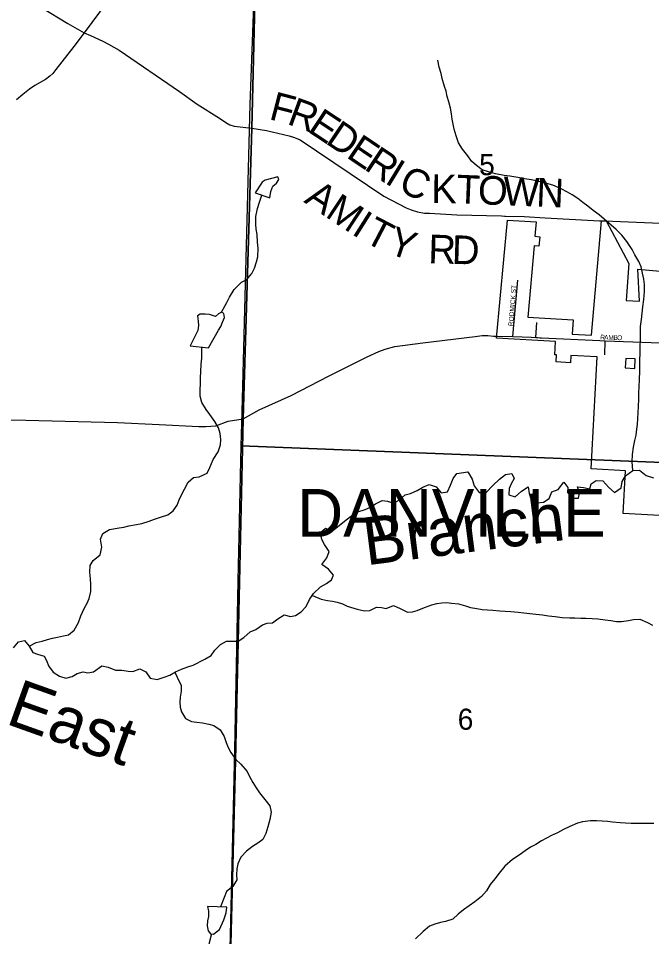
# Model space of a CAD drawing. Extents: x 1759416 to 2214760, y 252598 to 1116833.
# Drawn here: x 2027466 to 2034103, y 885483 to 895108 of the extents above; entities that cross this region are included whole.
import ezdxf

# ---------------------------------------------------------------- set-up
doc = ezdxf.new("R2010")
doc.units = 0
for name, color, linetype in [('GM_X_City_Street', 7, 'Continuous'), ('GM_X_City_Street_Text', 7, 'Continuous'), ('GM_X_Corporation', 7, 'Continuous'), ('GM_X_Corporation_Text', 7, 'Continuous'), ('GM_X_County_Road', 7, 'Continuous'), ('GM_X_County_Road_Text', 7, 'Continuous'), ('GM_X_Minor_Lake', 7, 'Continuous'), ('GM_X_Minor_River', 7, 'Continuous'), ('GM_X_Minor_River_Text', 7, 'Continuous'), ('GM_X_Section', 7, 'Continuous'), ('GM_X_Section_Text', 7, 'Continuous'), ('GM_X_Township', 7, 'Continuous'), ('GM_X_Township_Road', 7, 'Continuous'), ('GM_X_Township_ROW', 7, 'Continuous')]:
    doc.layers.add(name, color=color, linetype=linetype)

msp = doc.modelspace()

# ---------------------------------------------------------------- linework, layer by layer
at = {"layer": 'GM_X_City_Street'}
for points in [[(2032647.8, 891772.5), (2032699.7, 892363.5)], [(2032888.5, 891763.3), (2032898.6, 891921)], [(2032446.7, 891778.4), (2032478, 891776.3), (2032647.8, 891772.5), (2032746, 891770.2), (2032839.5, 891765.7), (2032888.5, 891763.3), (2032908.1, 891762.3), (2032932.8, 891760.9), (2032948.6, 891759.8), (2033559, 891730.3), (2033617.6, 891728.1), (2034387.6, 891699), (2034404.7, 891698.4)], [(2033612.6, 891579.4), (2033617.6, 891728.1)]]:
    msp.add_lwpolyline(points, dxfattribs=at)
at = {"layer": 'GM_X_Corporation'}
msp.add_lwpolyline([(2034633.1, 889872.7), (2033805.7, 889916.9), (2033829.4, 890366.4), (2033469.8, 890385.2), (2033531.4, 891558.8), (2033256.8, 891573.2), (2033252.9, 891498.3), (2033103, 891506.2), (2033107, 891581.1), (2033087, 891582.1), (2033094.4, 891721.9), (2032476, 891754.4), (2032591.4, 892992.4), (2032892.1, 892975.8), (2032880, 892823.7), (2032929.8, 892819.3), (2032921.1, 892719.7), (2032871.3, 892724.1), (2032805.8, 891976.8), (2033280, 891947.8), (2033270.8, 891798), (2033471, 891785.7), (2033578.2, 892985.8), (2033627.2, 892983.9), (2033864.7, 892537), (2033837.7, 892150.9), (2033976.7, 892143.1), (2033959.1, 892479.6), (2034233.1, 892455.7)], dxfattribs=at)
msp.add_lwpolyline([(2033926.2, 891437.8), (2033931.4, 891537.7), (2033831.5, 891542.9), (2033826.3, 891443.1)], close=True, dxfattribs=at)
at = {"layer": 'GM_X_County_Road'}
for points in [[(2028907.5, 896004.4), (2028898.5, 895993.8), (2028819.8, 895886.9), (2028546.2, 895485.6), (2028157, 894956.9), (2028046.7, 894812.8), (2027860.4, 894570.6), (2027826.3, 894528.5), (2027796.3, 894500.5), (2027752.2, 894468.5), (2027640.1, 894404.5), (2027582, 894366.6), (2027511.9, 894308.5), (2027445.8, 894252.5)], [(2027445, 895368.5), (2027583, 895294.1), (2027707, 895221.9), (2027983, 895053.3), (2028157, 894956.9), (2028222.9, 894926.8), (2028351, 894868.5), (2028411, 894836.4), (2028523, 894774.2), (2029154.9, 894342.7), (2029338.8, 894208.2), (2029574.8, 894061.7), (2029640.8, 894015.5), (2029682.8, 893993.4), (2029728.8, 893977.3), (2029912.9, 893957.5)], [(2029912.9, 893957.5), (2030067.9, 893933.9), (2030303, 893876.5), (2030361, 893860.4), (2030421, 893834.3), (2031296.9, 893244.2), (2031530.4, 893123.6), (2031582.2, 893102.2), (2031649.8, 893081.5), (2031724.2, 893067.6), (2031760, 893065.7), (2031776.2, 893064.8)], [(2031776.2, 893064.8), (2032061.1, 893050.2), (2032529.3, 893036.4), (2032562.3, 893035.4)], [(2032562.3, 893035.4), (2032570.8, 893035.1), (2032765.8, 893029.4), (2032985.4, 893018.7), (2033557.6, 892987.3)], [(2033557.6, 892987.3), (2033597.9, 892985.1), (2033610, 892984.6)], [(2033610, 892984.6), (2034448.4, 892950.1)], [(2029821.1, 890910.4), (2029990.8, 891005.5), (2030324.1, 891153.7), (2030722.6, 891359.6), (2031123, 891561.5), (2031245.2, 891615.4), (2031309.2, 891639.4), (2031413.3, 891669.4), (2031705.5, 891705.1), (2032253.9, 891772.6), (2032325.9, 891782.5), (2032386, 891782.4), (2032446.7, 891778.4)], [(2026673.8, 890913.6), (2027544.3, 890894.5), (2028504.8, 890873.3), (2028941, 890850.8), (2029359.2, 890830.3), (2029431.3, 890830.2), (2029537.3, 890836.1), (2029664.2, 890884.7), (2029821.1, 890910.4)]]:
    msp.add_lwpolyline(points, dxfattribs=at)
at = {"layer": 'GM_X_Minor_Lake'}
for points in [[(2030100.4, 893228.1), (2030112.1, 893294.3), (2030134, 893350.5), (2030169.9, 893380.7), (2030195.8, 893418.9), (2030183.7, 893446.9), (2030053.6, 893412.4), (2030021.6, 893390.2), (2029948, 893277.7)], [(2029948, 893277.7), (2030100.4, 893228.1)], [(2029457.4, 891652.7), (2029562.9, 891839.4), (2029586.7, 891879.6), (2029606.6, 891923.7), (2029626.4, 891973.9), (2029620.3, 892016), (2029594.2, 892029.9), (2029564.2, 892011.8), (2029532.3, 891983.6), (2029468.1, 892003.4), (2029424, 892007.3), (2029372, 892007.1), (2029344, 891989), (2029352.2, 891934.9), (2029354.4, 891886.8), (2029348.6, 891836.7), (2029265.1, 891674)], [(2029265.1, 891674), (2029457.4, 891652.7)], [(2029447.4, 885798.3), (2029459.6, 885750.2), (2029459.8, 885694.1), (2029450, 885648), (2029446.2, 885595.9), (2029454.4, 885541.8), (2029480.5, 885511.8), (2029510.6, 885507.9), (2029572.5, 885558.2), (2029620.2, 885658.6), (2029643.9, 885732.8), (2029649.7, 885793)], [(2029649.7, 885793), (2029447.4, 885798.3)]]:
    msp.add_lwpolyline(points, dxfattribs=at)
at = {"layer": 'GM_X_Minor_River'}
for points in [[(2033906.5, 890367.1), (2033900.2, 890459.3), (2033903.9, 890537.4), (2033913.6, 890611.6), (2033927.4, 890681.8), (2033939.2, 890740), (2033946.9, 890802.2), (2033954.8, 890852.3), (2033958.5, 890912.4), (2033962.3, 890976.6), (2033964.1, 891040.7), (2033967.8, 891114.9), (2033969.6, 891181), (2033973.3, 891245.2), (2033975, 891323.3), (2033978.7, 891411.5), (2033980.3, 891523.8), (2033982, 891599.9), (2033983.7, 891672.1), (2033985.5, 891736.2), (2033985.2, 891820.4), (2033986.9, 891878.5), (2033996.7, 891952.7), (2034004.4, 892016.9), (2034012.2, 892085.1), (2034021.9, 892159.3), (2034027.6, 892245.5), (2034029.3, 892319.6), (2034021.1, 892375.7), (2034008.9, 892437.8), (2033992.6, 892501.9), (2033968.3, 892559.9), (2033926, 892627.9), (2033897.8, 892683.9), (2033841.4, 892767.9), (2033789.1, 892833.9), (2033732.8, 892893.8), (2033678.5, 892939.7), (2033604.2, 893001.6), (2033551.9, 893047.5), (2033489.6, 893095.4), (2033433.4, 893139.3), (2033381.2, 893179.2), (2033331, 893219.1), (2033270.7, 893257), (2033220.6, 893286.9), (2033156.3, 893322.7), (2033068.1, 893358.5), (2033005.9, 893378.3), (2032921.7, 893398.1), (2032845.5, 893413.9), (2032771.4, 893425.7), (2032699.2, 893439.4), (2032617.1, 893455.2), (2032559, 893461), (2032466.8, 893478.7), (2032392.6, 893498.5), (2032326.4, 893520.3), (2032266.2, 893564.2), (2032215.9, 893612.1), (2032175.6, 893666.1), (2032119.3, 893738.1), (2032079, 893804.1), (2032052.7, 893876.1), (2032034.4, 893946.2), (2032024.2, 893998.3), (2032013.9, 894052.4), (2032005.7, 894106.4), (2031995.5, 894166.5), (2031979.2, 894234.6), (2031961, 894288.7), (2031948.7, 894344.8), (2031932.5, 894394.8), (2031908.2, 894478.9), (2031898, 894529), (2031877.7, 894597), (2031861.4, 894669.1)], [(2029596.7, 892028.6), (2029651.9, 892130.3), (2029679.7, 892184.5), (2029729.5, 892264.9), (2029805.3, 892343.3), (2029861.3, 892369.5), (2029913.1, 892433.8), (2029940.9, 892488), (2029962.7, 892554.2), (2029974.5, 892608.4), (2029978.2, 892698.6), (2029973.9, 892762.7), (2029967.6, 892842.9), (2029959.4, 892897), (2029955.2, 892949.1), (2029954.9, 893031.2), (2029972.6, 893113.5), (2029994.4, 893181.7), (2030017.9, 893255)], [(2027578.6, 888525.7), (2027652.5, 888566), (2027716.5, 888580.3), (2027772.6, 888596.5), (2027822.6, 888610.7), (2027874.6, 888620.9), (2027940.6, 888635.2), (2027990.7, 888647.4), (2028052.6, 888693.7), (2028096.3, 888774), (2028120.1, 888846.2), (2028155.9, 888922.5), (2028185.7, 888976.7), (2028209.6, 889026.9), (2028225.3, 889099.1), (2028225, 889175.3), (2028220.8, 889233.4), (2028216.5, 889303.5), (2028218.3, 889371.7), (2028250.1, 889423.9), (2028324, 889486.3), (2028341.7, 889566.5), (2028327.4, 889648.6), (2028351.2, 889706.8), (2028421.1, 889751.1), (2028521.2, 889767.5), (2028571.2, 889773.7), (2028625.3, 889787.9), (2028703.3, 889804.2), (2028761.4, 889814.4), (2028835.4, 889836.7), (2028893.4, 889859), (2028955.4, 889879.2), (2029031.4, 889905.5), (2029087.3, 889945.8), (2029131.2, 890004.1), (2029153, 890060.3), (2029176.8, 890114.5), (2029206.6, 890172.7), (2029244.4, 890247), (2029300.3, 890295.3), (2029362.4, 890301.5), (2029444.3, 890341.9), (2029472.2, 890400.1), (2029507.9, 890482.4), (2029561.7, 890564.7), (2029585.4, 890639), (2029587.2, 890695.1), (2029581, 890755.2), (2029562.7, 890817.3), (2029526.4, 890883.3), (2029472.1, 890957.2), (2029435.8, 891009.2), (2029389.5, 891081.2), (2029371.2, 891147.3), (2029372.9, 891213.4), (2029376.7, 891279.6), (2029376.5, 891341.7), (2029378.2, 891401.8), (2029381.9, 891484), (2029387.7, 891546.2), (2029389.3, 891660.2)], [(2027735.2, 888424), (2027763.4, 888370), (2027783.6, 888320), (2027831.9, 888254), (2027896.2, 888214.1), (2027964.4, 888192.3), (2028028.4, 888210.6), (2028082.3, 888240.8), (2028144.4, 888257.1), (2028194.5, 888249.2), (2028254.5, 888259.4), (2028342.4, 888321.9), (2028408.5, 888308.1), (2028484.8, 888276.2), (2028548.8, 888276.5), (2028617, 888266.7), (2028667.1, 888260.8), (2028739.1, 888291.1), (2028801.3, 888257.3), (2028847.6, 888193.3), (2028919.7, 888177.5), (2028995.7, 888203.8), (2029053.8, 888224.1), (2029113.7, 888258.3), (2029175.7, 888286.6), (2029243.7, 888310.9), (2029297.7, 888329.1), (2029421.6, 888391.7), (2029487.6, 888428), (2029525.4, 888484.2), (2029585.3, 888544.5), (2029647.2, 888580.8), (2029697.3, 888581), (2029771.4, 888579.2), (2029827.4, 888619.5), (2029897.2, 888677.9), (2029953.2, 888702.1), (2030025.1, 888750.5), (2030075.1, 888766.7), (2030129.2, 888770.9), (2030187.1, 888815.2), (2030251.1, 888855.5), (2030319.2, 888837.7), (2030369.3, 888847.9), (2030429.2, 888886.1), (2030481.1, 888942.4), (2030516.8, 889014.7), (2030560.7, 889079), (2030632.5, 889149.4), (2030696.4, 889183.7), (2030748.4, 889221.9), (2030770.2, 889272.1), (2030715.9, 889334.1), (2030647.6, 889381.9), (2030697.4, 889454.2), (2030723.2, 889520.5), (2030674.9, 889592.5), (2030646.6, 889644.5), (2030632.4, 889718.6), (2030684.3, 889764.9), (2030748.5, 889729), (2030810.4, 889777.3), (2030884.3, 889837.7), (2030948.2, 889888), (2031022.1, 889934.4), (2031100.1, 889960.7), (2031158.1, 889982.9), (2031210, 890019.2), (2031280, 890053.5), (2031334.1, 890045.7), (2031396.3, 890025.8), (2031460.2, 890060.1), (2031520.1, 890114.4), (2031574.1, 890128.7), (2031646.1, 890159), (2031706.1, 890195.2), (2031772.1, 890223.5), (2031844.3, 890197.7), (2031896.6, 890135.8), (2031962.6, 890144), (2031994.4, 890214.3), (2032024.2, 890284.5), (2032062, 890336.8), (2032178.1, 890355.2), (2032220.5, 890279.2), (2032242.8, 890207.1), (2032295.1, 890139.1), (2032367.2, 890137.4), (2032439, 890211.8), (2032508.9, 890276.1), (2032572.8, 890326.5), (2032638.8, 890336.7), (2032661.1, 890284.7), (2032629.2, 890230.5), (2032609.4, 890180.3), (2032607.6, 890112.1), (2032671.8, 890094.3), (2032739.7, 890152.7), (2032807.6, 890197), (2032817.9, 890126.9), (2032836.1, 890070.8)], [(2032836.1, 890070.8), (2032904.4, 890031), (2032970.4, 890037.2), (2033028.4, 890075.5), (2033056.2, 890145.7), (2033124.2, 890170), (2033184, 890246.4), (2033226.2, 890190.4), (2033222.4, 890136.3), (2033272.7, 890078.3), (2033336.8, 890078.5), (2033348.6, 890132.7), (2033326.3, 890198.8), (2033390.5, 890191), (2033456.6, 890177.2), (2033470.4, 890227.3), (2033522.4, 890263.6), (2033592.5, 890261.8), (2033654.8, 890189.9), (2033713.1, 890137.9), (2033785, 890188.3), (2033794.8, 890254.5), (2033828.6, 890312.7), (2033906.5, 890367.1), (2033974.6, 890371.3), (2034044.9, 890317.5), (2034121.1, 890291.7)], [(2030547.7, 889060), (2030641, 889021.1), (2030707.1, 889005.3), (2030757.2, 888997.5), (2030807.3, 888987.6), (2030861.5, 888971.8), (2030911.6, 888947.9), (2031015.9, 888916.2), (2031092.1, 888896.4), (2031150.1, 888902.6), (2031218.1, 888936.9), (2031270.2, 888933.1), (2031322.3, 888923.3), (2031398.3, 888953.6), (2031466.5, 888923.8), (2031544.8, 888883.9), (2031596.8, 888886.1), (2031646.8, 888900.3), (2031722.8, 888932.6), (2031798.8, 888960.9), (2031852.9, 888973.2), (2031904.9, 888981.3), (2031957, 888983.5), (2032007.1, 888979.7), (2032079.2, 888971.9), (2032151.4, 888950.1), (2032205.5, 888934.3), (2032271.7, 888920.5), (2032325.8, 888910.6), (2032383.9, 888906.8), (2032437.9, 888905), (2032512.1, 888899.2), (2032568.2, 888895.4), (2032628.3, 888889.6), (2032704.4, 888881.9), (2032762.5, 888876), (2032826.6, 888868.2), (2032888.7, 888862.4), (2032958.9, 888854.7), (2033021, 888846.9), (2033093.1, 888837.1), (2033165.2, 888829.3), (2033245.4, 888825.6), (2033297.5, 888823.8), (2033361.5, 888822), (2033411.6, 888822.1), (2033479.7, 888816.4), (2033539.8, 888812.6), (2033616, 888804.8), (2033676.1, 888795), (2033734.2, 888787.2), (2033786.3, 888785.3), (2033860.3, 888795.6), (2033914.4, 888807.8), (2033978.5, 888810), (2034058.7, 888776.2), (2034110.9, 888746.4)], [(2027414.4, 888511.1), (2027466.2, 888571.4), (2027530.3, 888585.7), (2027578.6, 888525.7), (2027616.9, 888461.7), (2027667, 888443.8), (2027735.2, 888424)], [(2029105.8, 888253.8), (2029129.9, 888202.3), (2029172.3, 888114.2), (2029170.6, 888054.1), (2029160.8, 887991.9), (2029157, 887941.8), (2029163.2, 887887.7), (2029175.4, 887837.7), (2029217.7, 887767.7), (2029281.9, 887737.8), (2029338, 887732), (2029396.1, 887724.2), (2029462.3, 887710.4), (2029514.4, 887694.5), (2029582.7, 887650.7), (2029623, 887578.7), (2029645.2, 887516.6), (2029663.5, 887464.5), (2029691.7, 887412.5), (2029746, 887340.6), (2029798.3, 887290.6), (2029862.7, 887214.7), (2029888.9, 887162.7), (2029923.2, 887098.7), (2029959.5, 887040.7), (2029991.7, 886988.7), (2030048, 886920.7), (2030102.4, 886854.7), (2030116.6, 886786.7), (2030102.9, 886710.4), (2030081.2, 886634.2), (2030061.4, 886564), (2030027.6, 886499.7), (2029975.7, 886463.5), (2029919.7, 886427.2), (2029855.8, 886378.9), (2029798, 886316.6), (2029766.2, 886246.3), (2029754.4, 886192.2), (2029752.6, 886130), (2029754.8, 886077.9), (2029713, 886009.6), (2029649.1, 885955.3), (2029623.3, 885893.1), (2029583.3, 885794.7)], [(2034126.7, 886670), (2034058.6, 886667.8), (2033948.4, 886667.4), (2033888.3, 886669.2), (2033830.3, 886673), (2033774.2, 886676.8), (2033694, 886682.6), (2033641.9, 886688.4), (2033583.8, 886694.2), (2033525.7, 886696), (2033463.6, 886697.8), (2033377.6, 886685.5), (2033325.6, 886671.3), (2033245.6, 886637), (2033177.6, 886606.7), (2033115.6, 886570.4), (2033053.7, 886544.1), (2033001.7, 886513.9), (2032947.7, 886485.6), (2032889.8, 886449.3), (2032831.8, 886419.1), (2032775.9, 886382.8), (2032714, 886336.5), (2032644, 886290.2), (2032564.2, 886219.8), (2032504.4, 886149.4), (2032460.5, 886089.1), (2032410.7, 886028.8), (2032372.9, 885962.6), (2032321, 885904.3), (2032251.2, 885845.9), (2032189.2, 885805.6), (2032131.3, 885763.3), (2032075.4, 885717), (2032019.5, 885666.8), (2031943.5, 885640.4), (2031891.5, 885632.2), (2031829.4, 885612), (2031773.4, 885591.8), (2031707.5, 885537.4), (2031629.7, 885459)], [(2029490.5, 885510.5), (2029464.9, 885417.6), (2029450.8, 885349.1)]]:
    msp.add_lwpolyline(points, dxfattribs=at)
at = {"layer": 'GM_X_Section'}
for points in [[(2029952.9, 895721.6), (2034997.1, 895554.1), (2034760.4, 893032.7), (2034659.9, 890435.6), (2029801.7, 890625.4), (2029811.2, 890985.1), (2029852.9, 892589.6), (2029894, 894203.9)], [(2034659.9, 890435.6), (2034485.3, 885005.2), (2029683.2, 885211.2), (2029695.7, 885793.1), (2029733.9, 887440.4), (2029770.1, 889211.7), (2029801.7, 890625.4)]]:
    msp.add_lwpolyline(points, close=True, dxfattribs=at)
at = {"layer": 'GM_X_Township'}
for points in [[(2029620.6, 882518), (2029741.2, 887327.4), (2029821.1, 890910.4), (2029912.9, 893957.5), (2029957.7, 895852.4), (2029992.2, 897192), (2030096.3, 901234.3), (2031090.7, 901194.9), (2031604.6, 901174.5), (2036524.9, 901030.8), (2040486.1, 900776.7), (2041723, 900684.1), (2049823.5, 900412.1)], [(2026468.6, 895963.3), (2027785.9, 895920.5), (2028819.8, 895886.9), (2029957.7, 895852.4), (2029912.9, 893957.5), (2029821.1, 890910.4), (2029741.2, 887327.4), (2029620.6, 882518)]]:
    msp.add_lwpolyline(points, dxfattribs=at)
at = {"layer": 'GM_X_Township_Road'}
msp.add_lwpolyline([(2029516.4, 876339.7), (2029509.2, 876366), (2029514, 876470.8), (2029512.1, 877091.6), (2029569.5, 879745.3), (2029620.5, 882518), (2029741.2, 887327.4), (2029821.1, 890910.4)], dxfattribs=at)
at = {"layer": 'GM_X_Township_ROW'}
msp.add_lwpolyline([(2029821.1, 890910.4), (2029912.9, 893957.5)], dxfattribs=at)

# ---------------------------------------------------------------- texts
at = {"layer": 'GM_X_City_Street_Text'}
for s, rotation, p in [('RODMICK ST', 85.29232, (2032650.5, 891880)), ('R', 355.69813, (2033562.6, 891743.4)), ('A', 357.40325, (2033603.7, 891740.3)), ('M', 358.50235, (2033648.7, 891738.3)), ('B', 358.5212, (2033701.5, 891736.9)), ('O', 358.52907, (2033741.1, 891735.9))]:
    msp.add_text(s, height=50, rotation=rotation, dxfattribs=at).set_placement(p)
at = {"layer": 'GM_X_Corporation_Text'}
msp.add_text('DANVILLE', height=500, rotation=0.00001, dxfattribs=at).set_placement((2030387.5, 889674.2))
at = {"layer": 'GM_X_County_Road_Text'}
for s, rotation, p in [('F', 345.4279, (2030083, 894053.1)), ('R', 339.88251, (2030271.5, 894004.5)), ('E', 326.5631, (2030486.5, 893928)), ('D', 326.05433, (2030673.2, 893804.8)), ('E', 326.04726, (2030892.2, 893657.3)), ('R', 326.38002, (2031079.9, 893531)), ('I', 328.57214, (2031295.7, 893387.8)), ('C', 335.25133, (2031434.4, 893305.6)), ('K', 359.41624, (2031792, 893172.4)), ('T', 357.68935, (2032053.6, 893169.7)), ('O', 357.68624, (2032277.8, 893160.7)), ('W', 357.68843, (2032541.6, 893150)), ('N', 357.68624, (2032889, 893136)), ('A', 326.00986, (2030450, 893185.1)), ('M', 326.47634, (2030671.1, 893036)), ('I', 327.70462, (2030948.4, 892852.4)), ('T', 332.43644, (2031076, 892773.1)), ('Y', 341.51423, (2031322.7, 892648.9)), ('R', 358.22977, (2031759, 892542.6)), ('D', 358.37859, (2032006.2, 892535))]:
    msp.add_text(s, height=300, rotation=rotation, dxfattribs=at).set_placement(p)
at = {"layer": 'GM_X_Minor_River_Text'}
for s, height, rotation, p in [('Branch', 500.05, 7.29538, (2031111.8, 889373.6)), ('East', 500.04, 340.32129, (2027320.7, 887718.6))]:
    msp.add_text(s, height=height, rotation=rotation, dxfattribs=at).set_placement(p)
at = {"layer": 'GM_X_Section_Text'}
for s, p in [('5', (2032294.7, 893464.1)), ('6', (2032070.3, 887651.2))]:
    msp.add_text(s, height=221, rotation=0.00001, dxfattribs=at).set_placement(p)

doc.saveas('drawing.dxf')
